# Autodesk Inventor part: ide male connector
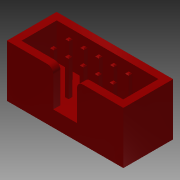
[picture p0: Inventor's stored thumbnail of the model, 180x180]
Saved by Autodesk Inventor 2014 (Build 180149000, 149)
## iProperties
Company: Autodesk Asia Pte. Ltd.
Created: 2005-12
Part Number: ide male connector
Document SubType Name: Modeling
Designer: Simon.Ng@autodesk.com
Density: 1 g/cm^3
Mass: 0.847102 g
Surface Area: 12.4518 cm^2
Volume: 0.847102 cm^3
Material: Generic
Appearance: Red
Title: PC Demo
Author: Simon.Ng@autodesk.com
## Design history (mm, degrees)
sketch "Sketch1"
  geometry: L1 (0, 5.943)-(0, -5.943) reference; L2 (-13.909, 0)-(13.909, 0) reference; L3 (-9.935, 4.245)-(9.935, 4.245); L4 (9.935, 4.245)-(9.935, -4.245); L5 (9.935, -4.245)-(-9.935, -4.245); L6 (-9.935, -4.245)-(-9.935, 4.245)
  constraints: 8 end point, 2 parallel, 1 horizontal, 1 perpendicular, 2 other
  dimensions: "d0" = 19.87 distance of L3.start L3.end; "d1" = 8.49 distance of L5.end L3.start
extrude "Extrusion1" new body sketch "Sketch1" distance "d2" = 8.89; taper "d3" = 0 deg
shell "Shell1" dims "d4" = 2.69, "d5" = 0.4, "d26" = 1.27, "d27" = 1.245
sketch "Sketch3"
  geometry: L1 (0, -8.89)-(19.87, -8.89) reference; L2 (9.935, 1.778)-(9.935, -10.668) reference; L3 (7.903, -8.89)-(11.967, -8.89); L4 (11.967, -8.89)-(11.967, -2.69); L5 (7.903, -2.69)-(7.903, -8.89); L6 (11.967, -2.69)-(7.903, -2.69)
  constraints: 8 end point, 2 perpendicular, 1 horizontal, 1 parallel, 1 point on line, 1 other
  dimensions: "d10" = 4.064 distance of L3.start L3.end; "d31" = 6.2 distance of L3.end L4.end
extrude "Extrusion3" cut sketch "Sketch3" distance "d16" = 1.778; taper "d17" = 0 deg
sketch "Sketch4"
  geometry: L1 (13.43, -1.57)-(14.06, -1.57); L2 (14.06, -1.57)-(14.06, -2.2); L3 (14.06, -2.2)-(13.43, -2.2); L4 (13.43, -2.2)-(13.43, -1.57); L5 (13.43, -4.2)-(14.06, -4.2); L6 (14.06, -4.2)-(14.06, -4.83); L7 (14.06, -4.83)-(13.43, -4.83); L8 (13.43, -4.83)-(13.43, -4.2); L9 (17.33, -6)-(0, -6) reference; L10 (8.665, -6)-(8.665, 1.245); L11 (13.745, -2.2)-(13.745, -4.2); L12 (6.633, 1.245)-(10.697, 1.245) reference
  constraints: 20 end point, 4 midpoint, 4 parallel, 3 perpendicular, 2 collinear, 2 horizontal
  dimensions: "d18" = 0.63 distance of L1.start L1.end; "d32" = 10.16 diameter of L11 L10
extrude "Extrusion4" join sketch "Sketch4" distance "d21" = 6.1; taper "d22" = 0 deg
chamfer "Chamfer1" distance "d28" = 0.15; stored, may be unused: second distance "d29" = 2, angle "d30" = 45 deg
pattern_linear "Rectangular Pattern2" dims "d35" = 2.54
fillet "Fillet1" dims "d43" = 1
body "Solid1"
